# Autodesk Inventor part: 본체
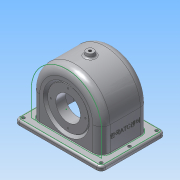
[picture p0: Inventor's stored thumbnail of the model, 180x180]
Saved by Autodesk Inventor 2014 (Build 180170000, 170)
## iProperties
Created: 2015-09
Part Number: 본체
Material: 알루미늄 6061
Document SubType Name: Modeling
Designer: sda1
Density: 2.71 g/cm^3
Appearance: 알루미늄 - 평지
Mass: 677.602 g
Surface Area: 897.181 cm^2
Volume: 250.038 cm^3
Author: sda1
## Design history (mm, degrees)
sketch "스케치7"
  geometry: L1 (0, 0)-(0, -40); L2 (-57, -40)-(57, -40); L3 (-57, -40)-(-57, 0); L4 (57, -40)-(57, 0); C1 r 51 at (0, 0); A1 r 57 centre (0, 0) between (-57, 0) and (57, 0)
  constraints: 8 end point, 2 centre point, 2 perpendicular, 2 point on circle, 1 coincident, 1 midpoint, 1 parallel, 1 vertical
  dimensions: "d18" = 40 distance of L1.end L1.start; "d19" = 114 distance of L2.start L2.end; "d20" = 102 diameter of C1; "d21" = 6 radial gap between concentric circles of C1 A1
extrude "돌출3" new body sketch "스케치7" distance "d22" = 77; taper "d23" = 0 deg
feature "쉘1" dims "d24" = 5
sketch "스케치11"
  geometry: L1 (0, 0)-(114, 0) reference; L2 (0, 0)-(0, -77) reference; L3 (114, -77)-(0, -77) reference; L4 (114, 0)-(114, -77) reference; L5 (5, -5)-(109, -5); L6 (109, -5)-(109, -72); L7 (109, -72)-(5, -72); L8 (5, -72)-(5, -5); L9 (-13, 13.5)-(127, 13.5); L10 (127, 13.5)-(127, -90.5); L11 (127, -90.5)-(-13, -90.5); L12 (-13, -90.5)-(-13, 13.5); L13 (57, 13.5)-(57, -90.5); L14 (57, 0)-(57, -77); 1 further point
  constraints: 20 end point, 5 midpoint, 4 parallel, 2 horizontal, 2 perpendicular
  dimensions: "d30" = 140 distance of L10.end L11.end; "d31" = 104 distance of L9.end L10.end
extrude "돌출5" join sketch "스케치11" distance "d32" = 7; taper "d33" = 0 deg
extrude "돌출6" cut sketch "스케치11" distance "d34" = 7; taper "d35" = 0 deg
node "작업 평면1"
node "작업 평면2"
sketch "스케치13"
  geometry: L1 (0, 0)-(0, -77); C1 r 6 at (0, -38.5)
  constraints: 2 end point, 1 centre point, 1 midpoint, 1 vertical
  dimensions: "d39" = 77 distance of L1.start L1.end; "d40" = 12 diameter of C1
extrude "돌출7" join sketch "스케치13" stored distance "d41" = 7; taper "d42" = 10 deg
sketch "스케치14"
  geometry: L1 (-57, -40)-(57, -40) reference; L2 (57, -40)-(57, 0) reference; L3 (-57, 0)-(-57, -40) reference; A1 r 57 centre (0, 0) between (57, 0) and (-57, 0) reference
sketch "스케치15"
  geometry: L1 (0, 0)-(0, -19); L2 (0, -19)-(28, -19); L3 (0, 0)-(43.943, 0); L4 (28, -19)-(43.943, 0)
  constraints: 8 end point, 1 parallel, 1 perpendicular, 1 vertical
  dimensions: "d43" = 19 distance of L1.start L1.end; "d44" = 50 deg angle of L2 L4; "d45" = 56 diameter of L2.end L1
revolve "회전1" sketch "스케치15" stored, may be unused: angle "d46" = 90 deg
sketch "스케치16"
  geometry: L1 (39.747, -5)-(28, -19) reference; L2 (0, 0)-(0, -3); L3 (0, -3)-(33, -3); L4 (37.416, 0)-(33, -5.263); L5 (0, 0)-(37.416, 0); L6 (33, -3)-(33, -5.263)
  constraints: 10 end point, 2 parallel, 2 perpendicular, 1 vertical
  dimensions: "d54" = 3 distance of L2.start L2.end; "d55" = 33 distance of L2.end L3.end; "d56" = 5 distance between parallel lines of L4 L1
revolve "회전2" sketch "스케치16" stored, may be unused: angle "d57" = 90 deg
sketch "스케치17"
  geometry: C1 r 31 at (0, 0); A1 r 57 centre (0, 0) between (57, 0) and (-57, 0) reference
  constraints: 1 centre point, 1 coincident
  dimensions: "d58" = 62 diameter of C1
extrude "돌출8" join sketch "스케치17" distance "d59" = 10; taper "d60" = 0 deg
sketch "스케치19"
  geometry: C1 r 20 at (0, 0); 1 further point
  constraints: 1 centre point, 1 coincident
  dimensions: "d62" = 40 diameter of C1
extrude "돌출9" cut sketch "스케치19" stored distance "d63" = 10; taper "d64" = 0 deg
sketch "스케치20"
  geometry: C1 r 6 at (0, 0) reference; 1 further point
hole "구멍1" sketch "스케치20" at (0, 0) diameter "d65" = 4.459; stored, may be unused: countersink angle "d69" = 90 deg, drill point angle "d71" = 118 deg; dims "d66" = 6, "d67" = 4, "d68" = 2, "d70" = 8
sketch "스케치21" dims "d73" = 56
  geometry: L1 (0, 0)-(0, 28); L2 (0, 37.416)-(0, 43.475); 1 further point
  constraints: 4 end point, 2 vertical, 2 vertical alignment, 1 coincident, 3 other
hole "구멍2" sketch "스케치21" at (0, 28) diameter "d74" = 2.459; stored, may be unused: countersink angle "d78" = 90 deg, drill point angle "d80" = 118 deg; dims "d75" = 7, "d76" = 4, "d77" = 2, "d79" = 9
fillet "모깎기1" dims "d84" = 0.5
sketch "스케치22" dims "d86" = 48
  geometry: L1 (0, 0)-(0, 24); C1 r 31 at (0, 0) reference
  constraints: 2 end point, 1 coincident, 1 vertical, 1 vertical alignment, 2 other
hole "구멍3" sketch "스케치22" at (0, 24) diameter "d87" = 2.459; stored, may be unused: countersink angle "d91" = 90 deg, drill point angle "d93" = 118 deg; dims "d88" = 6, "d89" = 4, "d90" = 2, "d92" = 8
fillet "모깎기2" dims "d97" = 14
fillet "모깎기3" dims "d98" = 3
fillet "모깎기4" dims "d99" = 7
fillet "모깎기5" dims "d100" = 3
fillet "모깎기6" dims "d101" = 1
fillet "모깎기7" dims "d102" = 9
sketch "스케치23"
  geometry: L1 (-20.5, -43)-(69.5, -43) reference; L2 (-20.5, -47)-(-20.5, -43) reference; L3 (69.5, -47)-(-20.5, -47) reference; L4 (69.5, -43)-(69.5, -47) reference; L5 (24.5, -47)-(24.5, -17); 2 further points
  constraints: 2 end point, 1 coincident, 1 midpoint, 1 parallel, 1 other
  dimensions: "d103" = 30 distance of L5.start L5.end
feature "엠보싱1" sketch "스케치23" dims "d104" = 0.5, "d105" = 0
sketch "스케치24"
  geometry: L1 (124, 83.5)-(124, -6.5) reference; L2 (-6, 87.5)-(120, 87.5) reference; L3 (-10, -6.5)-(-10, 83.5) reference; L4 (120, -10.5)-(-6, -10.5) reference; L5 (115, 14)-(115, 63) reference; L6 (14, -1)-(100, -1) reference; L7 (-1, 63)-(-1, 14) reference; L8 (100, 78)-(14, 78) reference; A1 r 4 centre (120, -6.5) between (120, -10.5) and (124, -6.5) reference; A2 r 4 centre (120, 83.5) between (124, 83.5) and (120, 87.5) reference; A3 r 4 centre (-6, 83.5) between (-6, 87.5) and (-10, 83.5) reference; A4 r 4 centre (-6, -6.5) between (-10, -6.5) and (-6, -10.5) reference; A5 r 15 centre (100, 63) between (115, 63) and (100, 78) reference; A6 r 15 centre (100, 14) between (100, -1) and (115, 14) reference; A7 r 15 centre (14, 14) between (-1, 14) and (14, -1) reference; A8 r 15 centre (14, 63) between (14, 78) and (-1, 63) reference; 1 further point
fillet "모깎기8" dims "d106" = 3
sketch "스케치25"
  geometry: L1 (100, 78)-(14, 78) reference; L2 (-6, 83.5)-(-6, 39.5); A1 r 4 centre (-6, 83.5) between (-6, 87.5) and (-10, 83.5) reference; A2 r 4 centre (-6, -6.5) between (-10, -6.5) and (-6, -10.5) reference; 1 further point
  constraints: 2 end point, 1 perpendicular
  dimensions: "d108" = 44 distance of L2.start L2.end
hole "구멍4" sketch "스케치25" at (-6, 39.5), (-6, 83.5), (-6, -6.5) diameter "d109" = 5; stored, may be unused: countersink angle "d113" = 90 deg, drill point angle "d115" = 118 deg; dims "d110" = 5, "d111" = 4, "d112" = 2, "d114" = 8
node "작업 평면3"
node "솔리드2"
pattern_circular "원형 패턴1" dims angle "d82" = 360 deg
pattern_circular "원형 패턴2" dims angle "d95" = 360 deg
mirror "대칭1"
node "투영된 루프1"
other parameters: "d38" = 6
